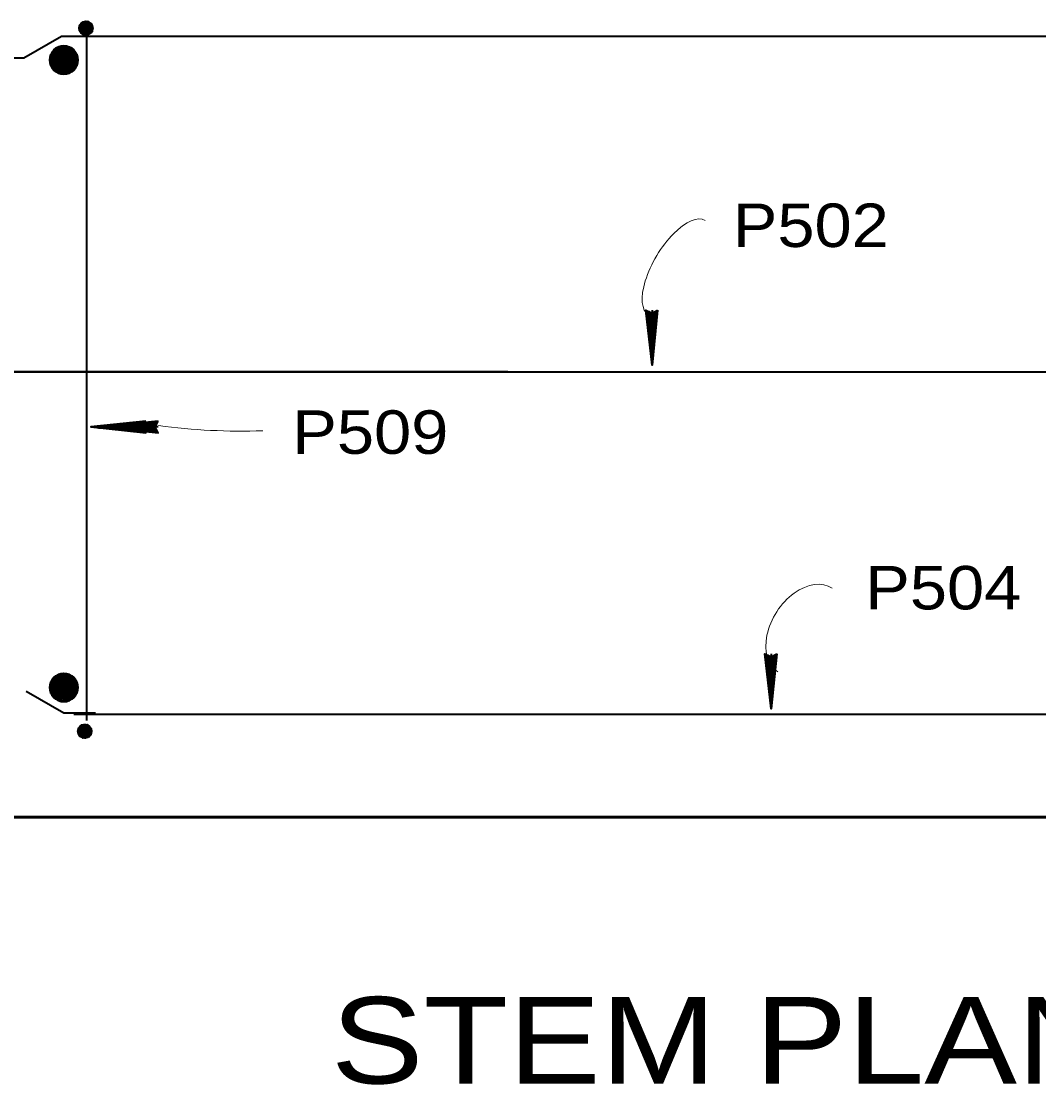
# Model space of a CAD drawing. Extents: x 14.14 to 17.34, y -1.61 to 0.38.
# Drawn here: x 14.6504 to 14.8456, y -0.6274 to -0.4235 of the extents above; entities that cross this region are included whole.
import ezdxf

# ---------------------------------------------------------------- set-up
doc = ezdxf.new("R2010")
doc.units = 0
doc.header["$LTSCALE"] = 0.0033
doc.layers.add('1', color=7, linetype='Continuous', lineweight=40)

msp = doc.modelspace()

# ---------------------------------------------------------------- linework, layer by layer
at = {"layer": '1'}
for p, q in [((14.661667, -0.424083), (14.66175, -0.425583)), ((14.663667, -0.423833), (14.66175, -0.424167)), ((14.66375, -0.424), (14.66175, -0.424333)), ((14.66375, -0.424083), (14.66175, -0.424417)), ((14.66375, -0.424167), (14.66175, -0.424583)), ((14.661833, -0.424083), (14.661917, -0.425583)), ((14.661917, -0.424083), (14.662, -0.425583)), ((14.662, -0.424083), (14.662083, -0.425583)), ((14.662083, -0.424083), (14.662167, -0.425583)), ((14.662167, -0.424083), (14.66225, -0.425583)), ((14.66225, -0.424083), (14.662333, -0.425583)), ((14.662333, -0.424083), (14.662417, -0.425583)), ((14.662333, -0.424083), (14.662417, -0.425583)), ((14.662417, -0.424083), (14.662583, -0.425583)), ((14.662583, -0.424083), (14.66275, -0.425583)), ((14.66275, -0.424), (14.662833, -0.4255)), ((14.662833, -0.424), (14.662917, -0.4255)), ((14.662917, -0.424), (14.663, -0.4255)), ((14.663, -0.424), (14.663083, -0.4255)), ((14.663083, -0.424), (14.663167, -0.4255)), ((14.663167, -0.424), (14.66325, -0.4255)), ((14.66325, -0.424), (14.663333, -0.4255)), ((14.663417, -0.424), (14.6635, -0.4255)), ((14.6635, -0.424), (14.663583, -0.4255)), ((14.663583, -0.424), (14.663667, -0.4255)), ((14.663667, -0.424), (14.66375, -0.4255)), ((14.66375, -0.424), (14.663833, -0.4255)), ((14.66375, -0.42425), (14.66175, -0.424667)), ((14.66375, -0.424417), (14.661833, -0.42475)), ((14.663833, -0.4245), (14.661833, -0.424833)), ((14.663833, -0.424583), (14.661833, -0.425)), ((14.663833, -0.424667), (14.661917, -0.425083)), ((14.663833, -0.42475), (14.661917, -0.425167)), ((14.663917, -0.424917), (14.661917, -0.425333)), ((14.663917, -0.425167), (14.661917, -0.4255)), ((14.663917, -0.42525), (14.662, -0.425583)), ((14.663917, -0.425333), (14.662, -0.425667)), ((14.664, -0.425417), (14.662, -0.42575)), ((14.662917, -0.42625), (14.662917, -0.557583)), ((14.6565, -0.429333), (14.661083, -0.4315)), ((14.65675, -0.42975), (14.660667, -0.4305)), ((14.65675, -0.429917), (14.660667, -0.430667)), ((14.65675, -0.430167), (14.660583, -0.430917)), ((14.656833, -0.429333), (14.66075, -0.43)), ((14.656833, -0.4295), (14.66075, -0.43025)), ((14.656917, -0.429), (14.66075, -0.429667)), ((14.658833, -0.429833), (14.660167, -0.428833)), ((14.660917, -0.429667), (14.659667, -0.4285)), ((14.656333, -0.432083), (14.660167, -0.432833)), ((14.656333, -0.43225), (14.660167, -0.433)), ((14.656417, -0.431583), (14.660333, -0.432333)), ((14.656417, -0.43175), (14.66025, -0.4325)), ((14.656417, -0.432), (14.66025, -0.432667)), ((14.6565, -0.431167), (14.660417, -0.431917)), ((14.656583, -0.43075), (14.660417, -0.4315)), ((14.656583, -0.430917), (14.660417, -0.431667)), ((14.656667, -0.430333), (14.6605, -0.431)), ((14.656667, -0.4305), (14.6605, -0.43125)), ((14.660667, -0.4325), (14.656917, -0.432917)), ((14.54025, -0.490667), (14.964167, -0.490667)), ((14.6565, -0.549667), (14.661083, -0.551833)), ((14.65675, -0.550083), (14.660667, -0.550833)), ((14.65675, -0.55025), (14.660667, -0.551)), ((14.65675, -0.5505), (14.660583, -0.55125)), ((14.656833, -0.549667), (14.66075, -0.550333)), ((14.656833, -0.549833), (14.66075, -0.550583)), ((14.656917, -0.549333), (14.66075, -0.55)), ((14.658833, -0.550167), (14.660167, -0.549167)), ((14.660917, -0.55), (14.659667, -0.548833)), ((14.656333, -0.552417), (14.660167, -0.553167)), ((14.656333, -0.552583), (14.660167, -0.553333)), ((14.656417, -0.551917), (14.660333, -0.552667)), ((14.656417, -0.552083), (14.66025, -0.552833)), ((14.656417, -0.552333), (14.66025, -0.553)), ((14.6565, -0.5515), (14.660417, -0.55225)), ((14.656583, -0.551083), (14.660417, -0.551833)), ((14.656583, -0.55125), (14.660417, -0.552)), ((14.656667, -0.550667), (14.6605, -0.551333)), ((14.656667, -0.550833), (14.6605, -0.551583)), ((14.660667, -0.552833), (14.656917, -0.55325)), ((14.883083, -0.556417), (14.6605, -0.556417)), ((14.663417, -0.558667), (14.6615, -0.559)), ((14.661417, -0.558917), (14.6615, -0.560417)), ((14.6635, -0.558833), (14.6615, -0.559167)), ((14.6635, -0.558917), (14.6615, -0.55925)), ((14.6635, -0.559), (14.6615, -0.559417)), ((14.6635, -0.559083), (14.6615, -0.5595)), ((14.661583, -0.558917), (14.661667, -0.560417)), ((14.6635, -0.55925), (14.661583, -0.559583)), ((14.663583, -0.559333), (14.661583, -0.559667)), ((14.663583, -0.559417), (14.661583, -0.559833)), ((14.661667, -0.558917), (14.66175, -0.560417)), ((14.663583, -0.5595), (14.661667, -0.559917)), ((14.663583, -0.559583), (14.661667, -0.56)), ((14.663667, -0.55975), (14.661667, -0.560167)), ((14.663667, -0.56), (14.661667, -0.560333)), ((14.66175, -0.558917), (14.661833, -0.560417)), ((14.663667, -0.560083), (14.66175, -0.560417)), ((14.663667, -0.560167), (14.66175, -0.5605)), ((14.66375, -0.56025), (14.66175, -0.560583)), ((14.661833, -0.558917), (14.661917, -0.560417)), ((14.661917, -0.558917), (14.662, -0.560417)), ((14.662, -0.558917), (14.662083, -0.560417)), ((14.662083, -0.558917), (14.662167, -0.560417)), ((14.662083, -0.558917), (14.662167, -0.560417)), ((14.662167, -0.558917), (14.662333, -0.560417)), ((14.662333, -0.558917), (14.6625, -0.560417)), ((14.6625, -0.558833), (14.662583, -0.560333)), ((14.662583, -0.558833), (14.662667, -0.560333)), ((14.662667, -0.558833), (14.66275, -0.560333)), ((14.66275, -0.558833), (14.662833, -0.560333)), ((14.662833, -0.558833), (14.662917, -0.560333)), ((14.662917, -0.558833), (14.663, -0.560333)), ((14.663, -0.558833), (14.663083, -0.560333)), ((14.663167, -0.558833), (14.66325, -0.560333)), ((14.66325, -0.558833), (14.663333, -0.560333)), ((14.663333, -0.558833), (14.663417, -0.560333)), ((14.663417, -0.558833), (14.6635, -0.560333)), ((14.6635, -0.558833), (14.663583, -0.560333))]:
    msp.add_line(p, q, dxfattribs=at)
at = {"layer": '1', "lineweight": 60}
for p, q in [((14.65675, -0.429333), (14.656583, -0.43225)), ((14.657, -0.429333), (14.65675, -0.43225)), ((14.657167, -0.429333), (14.657, -0.432333)), ((14.657333, -0.429333), (14.657083, -0.432333)), ((14.6575, -0.429333), (14.657333, -0.432333)), ((14.65775, -0.429333), (14.657583, -0.432333)), ((14.658, -0.429333), (14.65775, -0.432333)), ((14.658083, -0.429417), (14.657917, -0.432333)), ((14.65825, -0.429417), (14.658083, -0.432333)), ((14.658417, -0.429417), (14.65825, -0.432333)), ((14.658667, -0.429417), (14.658417, -0.432333)), ((14.658833, -0.429417), (14.658667, -0.432333)), ((14.659083, -0.4295), (14.658833, -0.432417)), ((14.659333, -0.4295), (14.659083, -0.432417)), ((14.6595, -0.4295), (14.659333, -0.432417)), ((14.659583, -0.4295), (14.659417, -0.432417)), ((14.65975, -0.4295), (14.659583, -0.432417)), ((14.659833, -0.4295), (14.659667, -0.432417)), ((14.660083, -0.429583), (14.659833, -0.4325)), ((14.66025, -0.429583), (14.660083, -0.4325)), ((14.660417, -0.429583), (14.660167, -0.4325)), ((14.660583, -0.429583), (14.660417, -0.4325)), ((14.660833, -0.429583), (14.660667, -0.4325)), ((14.661083, -0.4315), (14.660917, -0.429667)), ((14.661083, -0.4315), (14.656333, -0.43225)), ((14.65675, -0.549667), (14.656583, -0.552583)), ((14.657, -0.549667), (14.65675, -0.552583)), ((14.657167, -0.549667), (14.657, -0.552667)), ((14.657333, -0.549667), (14.657083, -0.552667)), ((14.6575, -0.549667), (14.657333, -0.552667)), ((14.65775, -0.549667), (14.657583, -0.552667)), ((14.658, -0.549667), (14.65775, -0.552667)), ((14.658083, -0.54975), (14.657917, -0.552667)), ((14.65825, -0.54975), (14.658083, -0.552667)), ((14.658417, -0.54975), (14.65825, -0.552667)), ((14.658667, -0.54975), (14.658417, -0.552667)), ((14.658833, -0.54975), (14.658667, -0.552667)), ((14.659083, -0.549833), (14.658833, -0.55275)), ((14.659333, -0.549833), (14.659083, -0.55275)), ((14.6595, -0.549833), (14.659333, -0.55275)), ((14.659583, -0.549833), (14.659417, -0.55275)), ((14.65975, -0.549833), (14.659583, -0.55275)), ((14.659833, -0.549833), (14.659667, -0.55275)), ((14.660083, -0.549917), (14.659833, -0.552833)), ((14.66025, -0.549917), (14.660083, -0.552833)), ((14.660417, -0.549917), (14.660167, -0.552833)), ((14.660583, -0.549917), (14.660417, -0.552833)), ((14.660833, -0.549917), (14.660667, -0.552833)), ((14.661083, -0.551833), (14.660917, -0.55)), ((14.661083, -0.551833), (14.656333, -0.552583)), ((14.60725, -0.576083), (14.747, -0.576083)), ((14.979333, -0.576083), (14.665583, -0.576083))]:
    msp.add_line(p, q, dxfattribs=at)
at = {"layer": '1', "lineweight": 35}
for p, q in [((14.770333, -0.479083), (14.771167, -0.486417)), ((14.7705, -0.479083), (14.77125, -0.486417)), ((14.770583, -0.479083), (14.771417, -0.486417)), ((14.77075, -0.479), (14.7715, -0.486333)), ((14.77225, -0.479083), (14.77125, -0.486917)), ((14.771417, -0.478833), (14.771417, -0.489417)), ((14.77225, -0.479083), (14.771417, -0.486917)), ((14.772417, -0.479083), (14.7715, -0.486917)), ((14.772417, -0.479083), (14.7715, -0.486917)), ((14.772333, -0.479083), (14.7715, -0.486917)), ((14.674333, -0.50125), (14.66375, -0.50125)), ((14.676667, -0.50125), (14.666083, -0.50125)), ((14.674083, -0.50025), (14.66625, -0.501167)), ((14.674083, -0.50025), (14.66625, -0.501167)), ((14.674083, -0.500333), (14.66625, -0.501167)), ((14.674083, -0.500417), (14.66625, -0.50125)), ((14.674083, -0.500417), (14.66625, -0.501417)), ((14.674083, -0.502083), (14.66675, -0.50125)), ((14.674083, -0.502167), (14.66675, -0.501417)), ((14.674083, -0.502333), (14.66675, -0.5015)), ((14.674167, -0.501917), (14.666833, -0.501167)), ((14.676417, -0.50025), (14.668583, -0.501167)), ((14.676417, -0.50025), (14.668583, -0.501167)), ((14.676417, -0.500333), (14.668583, -0.501167)), ((14.676417, -0.500417), (14.668583, -0.50125)), ((14.676417, -0.500417), (14.668583, -0.501417)), ((14.676417, -0.502083), (14.669083, -0.50125)), ((14.676417, -0.502167), (14.669083, -0.501417)), ((14.676417, -0.502333), (14.669083, -0.5015)), ((14.6765, -0.501917), (14.669167, -0.501167)), ((14.793167, -0.545), (14.794, -0.552333)), ((14.793333, -0.545), (14.794083, -0.552333)), ((14.793417, -0.545), (14.79425, -0.552333)), ((14.793583, -0.544917), (14.794333, -0.55225)), ((14.795083, -0.545), (14.794083, -0.552833)), ((14.79425, -0.54475), (14.79425, -0.555333)), ((14.795083, -0.545), (14.79425, -0.552833)), ((14.79525, -0.545), (14.794333, -0.552833)), ((14.79525, -0.545), (14.794333, -0.552833)), ((14.795167, -0.545), (14.794333, -0.552833))]:
    msp.add_line(p, q, dxfattribs=at)
at = {"layer": '1'}
for points in [[(14.664167, -0.424833), (14.661583, -0.4245), (14.663917, -0.424), (14.661583, -0.425083), (14.664, -0.4255), (14.662, -0.425833), (14.662, -0.42375), (14.662917, -0.426083), (14.662667, -0.4235), (14.663667, -0.425833), (14.663333, -0.4235), (14.6625, -0.426083), (14.664083, -0.424333), (14.661667, -0.424167), (14.663333, -0.426), (14.66225, -0.423583), (14.663917, -0.424), (14.664, -0.4255), (14.662917, -0.426083), (14.662, -0.425833), (14.661583, -0.425083), (14.661667, -0.424167), (14.66225, -0.423583), (14.662917, -0.424667), (14.66175, -0.425583), (14.663667, -0.425833), (14.662917, -0.424667), (14.664, -0.424167), (14.663, -0.4235), (14.662917, -0.424583), (14.662083, -0.425833), (14.664083, -0.424583), (14.66275, -0.42425), (14.662, -0.42375)], [(14.610417, -0.4305), (14.650917, -0.4305), (14.658167, -0.426333), (14.888, -0.426333)], [(14.656333, -0.43225), (14.658417, -0.4335), (14.660167, -0.433), (14.661083, -0.4315)], [(14.74375, -0.490667), (14.665167, -0.490667), (14.543833, -0.490667)], [(14.651333, -0.551917), (14.658583, -0.556083), (14.664667, -0.556083)], [(14.656333, -0.552583), (14.658417, -0.553833), (14.660167, -0.553333), (14.661083, -0.551833)], [(14.663917, -0.559667), (14.661333, -0.559333), (14.663667, -0.558833), (14.661333, -0.559917), (14.66375, -0.560333), (14.66175, -0.560667), (14.66175, -0.558583), (14.662667, -0.560917), (14.662417, -0.558333), (14.663417, -0.560667), (14.663083, -0.558333), (14.66225, -0.560917), (14.663833, -0.559167), (14.661417, -0.559), (14.663083, -0.560833), (14.662, -0.558417), (14.663667, -0.558833), (14.66375, -0.560333), (14.662667, -0.560917), (14.66175, -0.560667), (14.661333, -0.559917), (14.661417, -0.559), (14.662, -0.558417), (14.662667, -0.5595), (14.6615, -0.560417), (14.663417, -0.560667), (14.662667, -0.5595), (14.66375, -0.559), (14.66275, -0.558333), (14.662667, -0.559417), (14.661833, -0.560667), (14.663833, -0.559417), (14.6625, -0.559083), (14.66175, -0.558583)]]:
    msp.add_lwpolyline(points, dxfattribs=at)
at = {"layer": '1', "lineweight": 60}
for points in [[(14.655917, -0.431), (14.661083, -0.430333), (14.6565, -0.429333)], [(14.660167, -0.433), (14.660167, -0.428833), (14.6585, -0.4335), (14.659, -0.428333), (14.656917, -0.432917), (14.657667, -0.428417), (14.65925, -0.433417), (14.656083, -0.430083), (14.660917, -0.429667), (14.657667, -0.433333), (14.659667, -0.4285), (14.6565, -0.429333), (14.656333, -0.43225)], [(14.656917, -0.432917), (14.658417, -0.430667), (14.65625, -0.42975), (14.65825, -0.428333), (14.658417, -0.430583), (14.660083, -0.432917), (14.656083, -0.430583), (14.658833, -0.429833)], [(14.659667, -0.4285), (14.658417, -0.430667), (14.660667, -0.4325)], [(14.655917, -0.551333), (14.661083, -0.550667), (14.6565, -0.549667)], [(14.660167, -0.553333), (14.660167, -0.549167), (14.6585, -0.553833), (14.659, -0.548667), (14.656917, -0.55325), (14.657667, -0.54875), (14.65925, -0.55375), (14.656083, -0.550417), (14.660917, -0.55), (14.657667, -0.553667), (14.659667, -0.548833), (14.6565, -0.549667), (14.656333, -0.552583)], [(14.656917, -0.55325), (14.658417, -0.551), (14.65625, -0.550083), (14.65825, -0.548667), (14.658417, -0.550917), (14.660083, -0.55325), (14.656083, -0.550917), (14.658833, -0.550167)], [(14.659667, -0.548833), (14.658417, -0.551), (14.660667, -0.552833)]]:
    msp.add_lwpolyline(points, dxfattribs=at)
at = {"layer": '1', "lineweight": 35}
for points in [[(14.7725, -0.478833), (14.771417, -0.489417), (14.77025, -0.478833), (14.771417, -0.479417)], [(14.7715, -0.479583), (14.771583, -0.48425), (14.7715, -0.48425), (14.7715, -0.483333), (14.771583, -0.479583), (14.771667, -0.482583), (14.77175, -0.479417), (14.771833, -0.481667), (14.771917, -0.479417), (14.771667, -0.482917), (14.7715, -0.487583), (14.77125, -0.486667), (14.77125, -0.487917), (14.77125, -0.479583), (14.771083, -0.482), (14.771083, -0.479417), (14.7715, -0.48475), (14.770833, -0.479417)], [(14.674333, -0.500167), (14.66375, -0.50125), (14.674333, -0.502417), (14.67375, -0.50125)], [(14.673583, -0.501167), (14.668917, -0.501083), (14.668917, -0.501167), (14.669833, -0.501167), (14.673583, -0.501083), (14.670583, -0.501), (14.67375, -0.500917), (14.6715, -0.500833), (14.67375, -0.50075), (14.67025, -0.501), (14.665583, -0.501167), (14.6665, -0.501417), (14.66525, -0.501417), (14.673583, -0.501417), (14.671167, -0.501583), (14.67375, -0.501583), (14.668417, -0.501167), (14.67375, -0.501833)], [(14.676667, -0.500167), (14.666083, -0.50125), (14.676667, -0.502417), (14.676083, -0.50125)], [(14.675917, -0.501167), (14.67125, -0.501083), (14.67125, -0.501167), (14.672167, -0.501167), (14.675917, -0.501083), (14.672917, -0.501), (14.676083, -0.500917), (14.673833, -0.500833), (14.676083, -0.50075), (14.672583, -0.501), (14.667917, -0.501167), (14.668833, -0.501417), (14.667583, -0.501417), (14.675917, -0.501417), (14.6735, -0.501583), (14.676083, -0.501583), (14.67075, -0.501167), (14.676083, -0.501833)], [(14.795333, -0.54475), (14.79425, -0.555333), (14.793083, -0.54475), (14.79425, -0.545333)], [(14.794333, -0.5455), (14.794417, -0.550167), (14.794333, -0.550167), (14.794333, -0.54925), (14.794417, -0.5455), (14.7945, -0.5485), (14.794583, -0.545333), (14.794667, -0.547583), (14.79475, -0.545333), (14.7945, -0.548833), (14.794333, -0.5535), (14.794083, -0.552583), (14.794083, -0.553833), (14.794083, -0.5455), (14.793917, -0.547917), (14.793917, -0.545333), (14.794333, -0.550667), (14.793667, -0.545333)]]:
    msp.add_lwpolyline(points, close=True, dxfattribs=at)
for points in [[(14.7715, -0.479583), (14.77225, -0.479167), (14.772, -0.479417), (14.771667, -0.479583), (14.77175, -0.479833), (14.772083, -0.479667), (14.771333, -0.4795), (14.770833, -0.479333), (14.770417, -0.479083)], [(14.673583, -0.501167), (14.674, -0.500417), (14.67375, -0.500667), (14.673583, -0.501), (14.673333, -0.500917), (14.6735, -0.500583), (14.673667, -0.501333), (14.673833, -0.501833), (14.674083, -0.50225)], [(14.675917, -0.501167), (14.676333, -0.500417), (14.676083, -0.500667), (14.675917, -0.501), (14.675667, -0.500917), (14.675833, -0.500583), (14.676, -0.501333), (14.676167, -0.501833), (14.676417, -0.50225)], [(14.794333, -0.5455), (14.795083, -0.545083), (14.794833, -0.545333), (14.7945, -0.5455), (14.794583, -0.54575), (14.794917, -0.545583), (14.794167, -0.545417), (14.793667, -0.54525), (14.79325, -0.545)]]:
    msp.add_lwpolyline(points, dxfattribs=at)
at = {"layer": '1'}
for centre in [(14.662833, -0.424783), (14.662583, -0.559617)]:
    msp.add_circle(centre, 0.00132, dxfattribs=at)
at = {"layer": '1', "lineweight": 60}
for centre in [(14.658583, -0.4309), (14.658583, -0.551233)]:
    msp.add_circle(centre, 0.00264, dxfattribs=at)
at = {"layer": '1', "lineweight": 13}
msp.add_arc((14.692743, -0.381636), 0.120431, 262.36857, 271.90662, dxfattribs=at)
for centre, major_axis, ratio in [((14.776167, -0.470708), (0.005417, 0.009042), 0.424401), ((14.800792, -0.540208), (0.005208, 0.008042), 0.67679)]:
    msp.add_ellipse(centre, major_axis=major_axis, ratio=ratio, start_param=0, end_param=3.1415927, dxfattribs=at)

# ---------------------------------------------------------------- texts
at = {"layer": '1'}
for s, height, width, p in [('P502', 0.008334, 1.15, (14.786917, -0.46675)), ('P509', 0.008334, 1.15, (14.702417, -0.506417)), ('P504', 0.008334, 1.15, (14.812333, -0.53625)), ('STEM PLAN VIEW', 0.01658, 1.2, (14.709833, -0.627167))]:
    msp.add_text(s, height=height, dxfattribs=dict(at, width=width)).set_placement(p)

doc.saveas('drawing.dxf')
